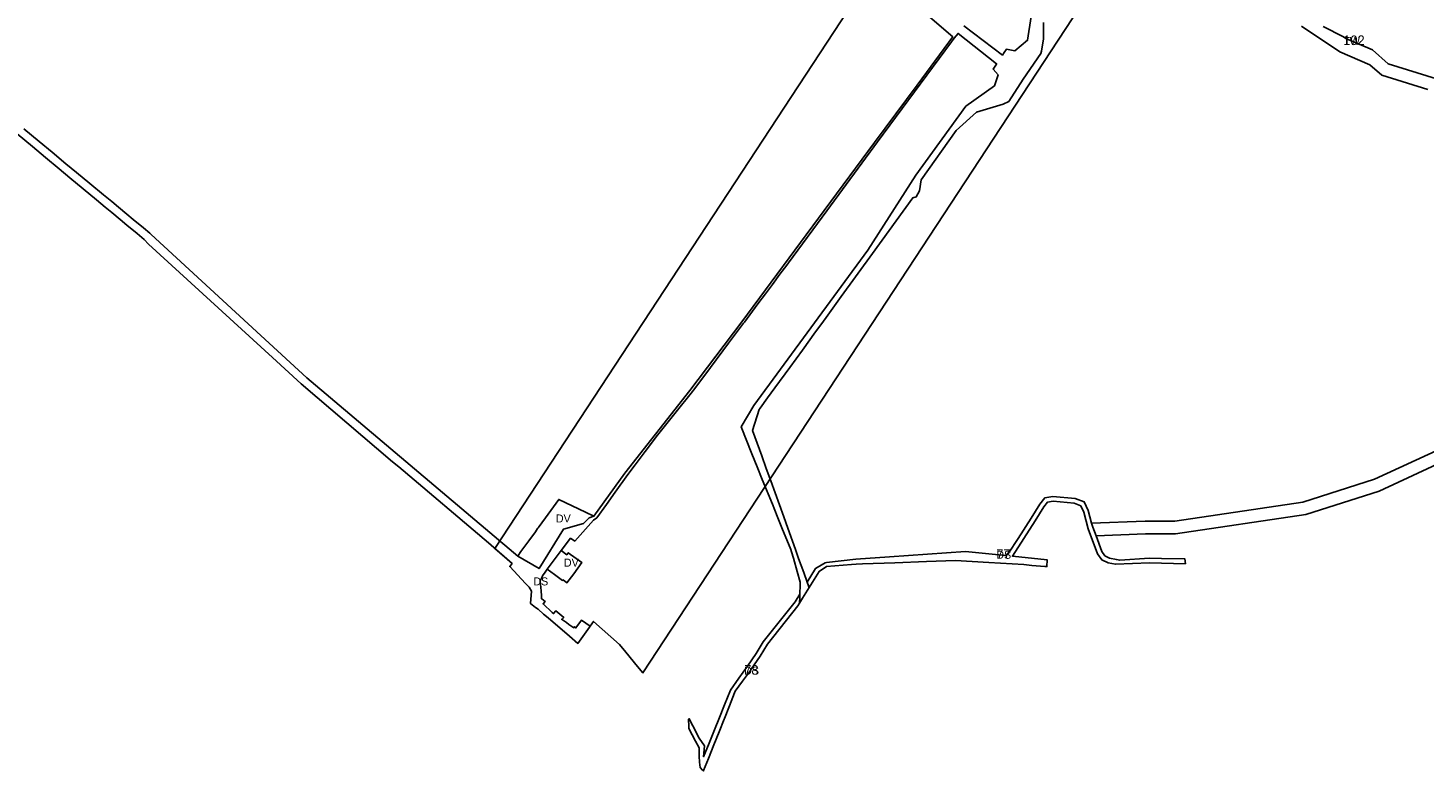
# Model space of a CAD drawing. Extents: x -537034 to -534353, y -1176562 to -1173176.
# Drawn here: x -536157 to -535284, y -1176562 to -1176098 of the extents above; entities that cross this region are included whole.
import ezdxf

# ---------------------------------------------------------------- set-up
doc = ezdxf.new("R2010")
doc.units = 0
for name, color, linetype in [('90320013', 7, 'Continuous'), ('90320023', 7, 'Continuous'), ('90350013', 7, 'Continuous'), ('90350033', 7, 'Continuous'), ('90390023', 7, 'Continuous'), ('ID_navrh', 7, 'Continuous')]:
    doc.layers.add(name, color=color, linetype=linetype)

msp = doc.modelspace()

# ---------------------------------------------------------------- linework, layer by layer
at = {"layer": '90320013'}
for points in [[(-536159.43, -1176160.85), (-536149.92, -1176168.73), (-536141.8, -1176175.46), (-536133.19, -1176182.6), (-536126.54, -1176188.11), (-536118.23, -1176195), (-536109.82, -1176201.98), (-536104.56, -1176206.34), (-536100.41, -1176209.78), (-536095.19, -1176214.11), (-536091.15, -1176217.46), (-536084.8, -1176222.72), (-536080.82, -1176226.03), (-536079.97, -1176226.81), (-536011.45, -1176289.95), (-535982.72, -1176316.41), (-535850.75, -1176427.84), (-535837.49, -1176435.62), (-535822.24, -1176411.03), (-535809.83, -1176407.52), (-535806.27, -1176404), (-535803.35, -1176402.91), (-535803.32, -1176402.89), (-535784.04, -1176376), (-535743.34, -1176324.33), (-535710.77, -1176281.42), (-535659.3, -1176211.77), (-535627.85, -1176169.35), (-535601.29, -1176133.46), (-535581.49, -1176106.71), (-535579.87, -1176104.45), (-535579.75, -1176104.28), (-535579.07, -1176103.38), (-535616.5, -1176070.96)], [(-535522.4, -1176094.37), (-535522.26, -1176104.52), (-535523.65, -1176112.33), (-535523.9, -1176113.7), (-535534.97, -1176129.73), (-535543.93, -1176143.64), (-535547.48, -1176145.43), (-535564.25, -1176150.34), (-535576.94, -1176161.89), (-535598.85, -1176192.74), (-535599.72, -1176199.54), (-535601.8, -1176203.42), (-535604.01, -1176203.9), (-535629.13, -1176238.73), (-535648.75, -1176265.71), (-535657.12, -1176277.22), (-535660.94, -1176282.47), (-535664.71, -1176287.65), (-535673.01, -1176299.08), (-535680.9, -1176309.93), (-535690.21, -1176322.74), (-535694.79, -1176329.04), (-535699.43, -1176335.44), (-535700.03, -1176336.26), (-535704.11, -1176349.3), (-535698.43, -1176365.11), (-535695.55, -1176373.11), (-535692.81, -1176380.73), (-535687.39, -1176395.81), (-535684.69, -1176403.31), (-535682.13, -1176410.42), (-535677.31, -1176423.83), (-535676.47, -1176426.16), (-535675.32, -1176429.34), (-535672.16, -1176438.09), (-535669.94, -1176444.21), (-535669.15, -1176446.4), (-535668.75, -1176447.51), (-535672.87, -1176454.11), (-535674.81, -1176457.22), (-535674.67, -1176453.74), (-535674.59, -1176451.72), (-535674.36, -1176445.88), (-535674.3, -1176444.24), (-535676.19, -1176437.59), (-535678.58, -1176429.21), (-535679.7, -1176425.28), (-535680.29, -1176423.83), (-535685.77, -1176410.3), (-535688.76, -1176402.9), (-535691.75, -1176395.49), (-535698.04, -1176379.96), (-535701.24, -1176372.05), (-535704.53, -1176363.92), (-535711.31, -1176347.15), (-535703.24, -1176333.84), (-535632.19, -1176236.64), (-535602.1, -1176189.88), (-535570.8, -1176146.67), (-535552.89, -1176133.89), (-535550.75, -1176127.07), (-535553.82, -1176123.5), (-535551.69, -1176120.31), (-535551.61, -1176120.18), (-535575.75, -1176101.2), (-535578.1, -1176104.22), (-535579.75, -1176106.46), (-535626.09, -1176169.01), (-535657.63, -1176212.04), (-535681.71, -1176244.51), (-535682.81, -1176246), (-535686.99, -1176251.65), (-535691.75, -1176258.07), (-535696.1, -1176263.94), (-535700.74, -1176270.21), (-535709.27, -1176281.73), (-535709.73, -1176282.34), (-535719.11, -1176294.83), (-535730.4, -1176309.95), (-535735.81, -1176317.18), (-535741.07, -1176324.23), (-535741.6, -1176324.94), (-535752.68, -1176338.75), (-535764.34, -1176353.29), (-535764.83, -1176353.9), (-535771.34, -1176362.59), (-535777.52, -1176370.83), (-535782.02, -1176376.84), (-535789.9, -1176387.82), (-535795.48, -1176395.6), (-535801.4, -1176403.85), (-535803.56, -1176405.4), (-535815.25, -1176418.52), (-535817.82, -1176416.66), (-535823.71, -1176424.37), (-535832.45, -1176436.05), (-535833.72, -1176437.83), (-535835.49, -1176440.1), (-535835.37, -1176440.19), (-535835.7, -1176440.88), (-535836.91, -1176443.39), (-535836.3, -1176449.47), (-535835.98, -1176452.6), (-535836.06, -1176454.57), (-535835.85, -1176454.59), (-535833.71, -1176456.25), (-535834.99, -1176457.72), (-535829.43, -1176463.13), (-535828.46, -1176463.79), (-535826.97, -1176462.05), (-535822.14, -1176466.2), (-535823.13, -1176467.38), (-535823.43, -1176467.31), (-535820.4, -1176469.45), (-535818.84, -1176470.52), (-535815.79, -1176472.66), (-535815.39, -1176472.01), (-535814.51, -1176472.78), (-535810.99, -1176467.85), (-535805.66, -1176471.65), (-535807.04, -1176473.64), (-535813.34, -1176482.47), (-535818.56, -1176477.96), (-535831.94, -1176466.46), (-535834.68, -1176464.1), (-535838.2, -1176461.07), (-535839.73, -1176459.91), (-535842.84, -1176457.56), (-535842.29, -1176449.79), (-535843.77, -1176447.3), (-535846.01, -1176444.91), (-535855.86, -1176434.39), (-535854.45, -1176432.58), (-535869.1, -1176419.6), (-535925.23, -1176372.1), (-535929.15, -1176368.86), (-535986.21, -1176320.1), (-536004.1, -1176303.75), (-536081.65, -1176232.88), (-536084.31, -1176229.96), (-536088.79, -1176226.24), (-536095.13, -1176220.97), (-536099.27, -1176217.53), (-536104.54, -1176213.15), (-536108.71, -1176209.68), (-536114.02, -1176205.27), (-536122.48, -1176198.24), (-536130.74, -1176191.38), (-536137.48, -1176185.78), (-536146.04, -1176178.67), (-536154.18, -1176171.91), (-536163.69, -1176164.01)], [(-535572.04, -1176096.44), (-535547.96, -1176114.72), (-535546.85, -1176113.06), (-535545.43, -1176110.93), (-535540.24, -1176112.01), (-535532.28, -1176105.42), (-535530.06, -1176090.53)]]:
    msp.add_lwpolyline(points, dxfattribs=at)
at = {"layer": '90320023'}
for points in [[(-535492.23, -1176407.19), (-535491.5, -1176409.86), (-535489.51, -1176415.24), (-535485.87, -1176425.04), (-535483.96, -1176427.79), (-535480.98, -1176429.21), (-535476.78, -1176430.03), (-535474.65, -1176430.44), (-535456.08, -1176429.16), (-535448.49, -1176429.32), (-535433.95, -1176429.62), (-535433.67, -1176432.62), (-535448.55, -1176432.32), (-535456, -1176432.17), (-535477.35, -1176432.97), (-535481.93, -1176432.09), (-535485.97, -1176430.15), (-535488.55, -1176426.44), (-535494.36, -1176410.78), (-535497.18, -1176400.37), (-535499.04, -1176396.42), (-535503.24, -1176394.88), (-535516.31, -1176393.59), (-535519.86, -1176394.24), (-535522.04, -1176397.14), (-535527.53, -1176405.86), (-535541.79, -1176427.98), (-535519.96, -1176430.27), (-535520.14, -1176434.4), (-535521.58, -1176434.42), (-535529.7, -1176433.67), (-535534.68, -1176433.18), (-535556.56, -1176431.9), (-535577.27, -1176430.68), (-535595.45, -1176431.32), (-535615.18, -1176432.01), (-535635.36, -1176432.72), (-535639.44, -1176432.86), (-535642.39, -1176433.18), (-535657.92, -1176434.41), (-535662.5, -1176437.48), (-535668.75, -1176447.51), (-535669.15, -1176446.4), (-535669.94, -1176444.21), (-535664.74, -1176435.61), (-535663.81, -1176434.93), (-535658.77, -1176432.03), (-535657.85, -1176431.79), (-535639.55, -1176429.82), (-535618.53, -1176428.31), (-535571.1, -1176424.91), (-535546.07, -1176427.53), (-535544.12, -1176426.06), (-535538.13, -1176416.77), (-535530.06, -1176404.25), (-535524.51, -1176395.44), (-535521.55, -1176391.5), (-535516.43, -1176390.57), (-535502.56, -1176391.94), (-535496.85, -1176394.02), (-535494.36, -1176399.33)], [(-535674.59, -1176451.72), (-535674.67, -1176453.74), (-535674.81, -1176457.22), (-535675.87, -1176458.92), (-535694.78, -1176482.86), (-535699.45, -1176490.49), (-535704.9, -1176498.43), (-535705.52, -1176499.3), (-535710.34, -1176505.96), (-535714.92, -1176512.29), (-535715.34, -1176513.34), (-535718.6, -1176521.51), (-535721.7, -1176529.29), (-535721.93, -1176529.86), (-535725.02, -1176537.6), (-535728.31, -1176545.84), (-535731.73, -1176554.4), (-535734.72, -1176561.9), (-535734.85, -1176562.23), (-535735.32, -1176561.72), (-535736.89, -1176560.03), (-535737.27, -1176556.72), (-535737.4, -1176552.99), (-535737.57, -1176547.8), (-535739.84, -1176543.43), (-535743.9, -1176535.62), (-535743.96, -1176534.12), (-535744.12, -1176529.72), (-535743.81, -1176529.37), (-535743.29, -1176530.39), (-535741.44, -1176533.9), (-535737.41, -1176541.67), (-535734.17, -1176546.44), (-535734.75, -1176553.24), (-535731.3, -1176544.75), (-535727.94, -1176536.52), (-535724.82, -1176528.73), (-535721.59, -1176520.75), (-535718.01, -1176511.69), (-535712.69, -1176504.06), (-535707.35, -1176496.57), (-535701.92, -1176488.79), (-535697.41, -1176481.4), (-535677.45, -1176456.39)]]:
    msp.add_lwpolyline(points, close=True, dxfattribs=at)
at = {"layer": '90350013'}
for points in [[(-535850.75, -1176427.84), (-535848.98, -1176425.04), (-535844.01, -1176418.3), (-535839.87, -1176412.68), (-535838.55, -1176410.7), (-535838.17, -1176410.22), (-535837.49, -1176409.37), (-535831.85, -1176401.58), (-535825.21, -1176392.4), (-535808.48, -1176400.44), (-535803.35, -1176402.91), (-535806.27, -1176404), (-535809.83, -1176407.52), (-535822.24, -1176411.03), (-535837.49, -1176435.62)], [(-535832.45, -1176436.05), (-535823.71, -1176424.37), (-535820.26, -1176426.99), (-535819.35, -1176425.76), (-535810.92, -1176431.84), (-535815.92, -1176438.86), (-535820.19, -1176444.54), (-535822.57, -1176442.7), (-535822.86, -1176443.09), (-535827.81, -1176439.46)]]:
    msp.add_lwpolyline(points, close=True, dxfattribs=at)
at = {"layer": '90350033'}
msp.add_lwpolyline([(-535199.83, -1175627.8), (-535772.63, -1176500.85), (-535775.96, -1176496.83), (-535783.4, -1176487.84), (-535787.33, -1176483.09), (-535803.54, -1176468.74), (-535807.04, -1176473.64), (-535813.34, -1176482.47), (-535818.56, -1176477.96), (-535831.94, -1176466.46), (-535834.68, -1176464.1), (-535838.2, -1176461.07), (-535839.73, -1176459.91), (-535842.84, -1176457.56), (-535842.29, -1176449.79), (-535843.77, -1176447.3), (-535846.01, -1176444.91), (-535855.86, -1176434.39), (-535854.45, -1176432.58), (-535865.15, -1176423.1), (-535300.19, -1175562.02), (-535233.47, -1175460.12)], dxfattribs=at)
at = {"layer": '90390023'}
for points in [[(-535282.17, -1176136.28), (-535310.89, -1176127.38), (-535318.31, -1176120.82), (-535337.12, -1176112.77), (-535361.09, -1176096.62)], [(-535347.64, -1176096.92), (-535334.8, -1176103.36), (-535333.44, -1176104.28), (-535316.8, -1176111.47), (-535306.88, -1176120.25), (-535270.7, -1176131.4)], [(-535270.44, -1176367.75), (-535312.56, -1176387.25), (-535358.44, -1176401.88), (-535439.75, -1176414), (-535458.56, -1176414), (-535489.51, -1176415.24), (-535491.5, -1176409.86), (-535492.23, -1176407.19), (-535458.72, -1176406), (-535440.34, -1176406), (-535360.25, -1176394.06), (-535315.47, -1176379.78), (-535274.29, -1176360.72)]]:
    msp.add_lwpolyline(points, dxfattribs=at)

# ---------------------------------------------------------------- texts
at = {"layer": '90320013'}
msp.add_text('DS', height=5, rotation=360, dxfattribs=at).set_placement((-535841.09, -1176446.19))
at = {"layer": '90320023'}
for rotation, p in [(360, (-535551.81, -1176429.55)), (0, (-535709.36, -1176501.99))]:
    msp.add_text('DS', height=5, rotation=rotation, dxfattribs=at).set_placement(p)
at = {"layer": '90350013'}
for p in [(-535827.05, -1176406.86), (-535822.02, -1176434.46)]:
    msp.add_text('DV', height=5, rotation=0, dxfattribs=at).set_placement(p)
at = {"layer": '90390023'}
msp.add_text('TW', height=5, rotation=0, dxfattribs=at).set_placement((-535335.01, -1176108.47))
at = {"layer": 'ID_navrh'}
for s, rotation, p in [('102', 0, (-535335.01, -1176108.47)), ('77', 360, (-535551.81, -1176429.55)), ('78', 0, (-535709.36, -1176501.99))]:
    msp.add_text(s, height=6, rotation=rotation, dxfattribs=at).set_placement(p)

doc.saveas('drawing.dxf')
